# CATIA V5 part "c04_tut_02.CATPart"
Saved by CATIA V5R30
Part number: Part1
Bounding box of the stored display mesh (mm): x 0 to 0, y -110 to 125.99, z -120 to 120
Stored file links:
  D:\PROJECTS\CATIA V56R 2020\Resources\c04\c04_tut_02.CATPart
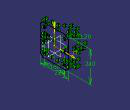
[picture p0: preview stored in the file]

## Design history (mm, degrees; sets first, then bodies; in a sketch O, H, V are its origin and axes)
Body1 (main body)
  Sketch1 on yz-plane, origin (0, 0, 0), H (0, 1, 0), V (0, 0, 1)
    construction line L1 (0, 89.6704) -> (0, 0)
    point P1 (0, 89.6704)
    axis line L2 (0, 0) -> (125.9901, 0)
    point P3 (0, 120)
    line L3 (0, 120) -> (90, 120)
    point P4 (90, 120)
    line L4 (90, 120) -> (110, 100)
    point P5 (110, 100)
    line L5 (110, 100) -> (110, 10)
    point P6 (110, 10)
    line L6 (110, 10) -> (80, 10)
    point P7 (80, 10)
    line L7 (80, 10) -> (80, 0)
    point P8 (80, 0)
    circle A1 centre (80, 90) radius 10
    point P9 (80, 90)
    point P10 (90, -120)
    point P11 (0, -120)
    line L8 (0, -120) -> (90, -120)
    point P12 (110, -100)
    line L9 (90, -120) -> (110, -100)
    point P13 (110, -10)
    line L10 (110, -100) -> (110, -10)
    point P14 (80, -10)
    line L11 (110, -10) -> (80, -10)
    point P15 (80, 0)
    line L12 (80, -10) -> (80, 0)
    circle A2 centre (80, -90) radius 10
    point P17 (-90, 120)
    point P18 (0, 120)
    line L13 (0, 120) -> (-90, 120)
    point P19 (-110, 100)
    line L14 (-90, 120) -> (-110, 100)
    point P20 (-110, 10)
    line L15 (-110, 100) -> (-110, 10)
    circle A3 centre (-80, 90) radius 10
    point P22 (-80, 10)
    line L16 (-110, 10) -> (-80, 10)
    point P23 (-80, 0)
    line L17 (-80, 10) -> (-80, 0)
    point P24 (-80, 0)
    point P25 (-80, -10)
    line L18 (-80, -10) -> (-80, 0)
    point P26 (-110, -10)
    line L19 (-110, -10) -> (-80, -10)
    point P27 (-110, -100)
    line L20 (-110, -100) -> (-110, -10)
    point P28 (-90, -120)
    line L21 (-90, -120) -> (-110, -100)
    circle A4 centre (-80, -90) radius 10
    point P30 (0, -120)
    line L22 (0, -120) -> (-90, -120)
    distance L20 L10 = 220
    distance L3 L8 = 240
    distance L5 P9 = 30
    distance L3 P9 = 30
    radius A1 = 10
    length L14 V = 20
    length L14 H = 20
    distance L6 L11 = 20
    distance L18 L12 = 160
    coincidence: P1 V, P3 L1, P8 L2
    vertical: L1 V, L5 V, L7 V
    horizontal: L2 H, L3 H, L6 H
    symmetry: P4 P10 L2, P3 P11 L2, L3 L8 L2, P5 P12 L2, L4 L9 L2, P6 P13 L2, L5 L10 L2, P7 P14 L2, L6 L11 L2, P8 P15 L2, L7 L12 L2, A1 A2 L2, P4 P17 L1, P3 P18 L1, L3 L13 L1, P5 P19 L1, L4 L14 L1, P6 P20 L1, L5 L15 L1, A1 A3 L1, P7 P22 L1, L6 L16 L1, P8 P23 L1, L7 L17 L1, P15 P24 L1, P14 P25 L1, L12 L18 L1, P13 P26 L1, L11 L19 L1, P12 P27 L1, L10 L20 L1, P10 P28 L1, L9 L21 L1, A2 A4 L1, P11 P30 L1, L8 L22 L1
